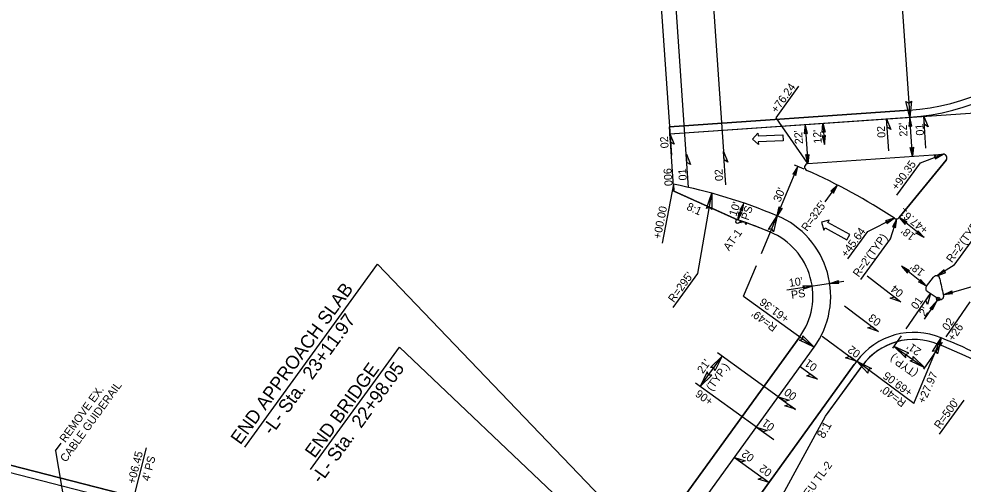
# Model space of a CAD drawing. Extents: x 1183930 to 1185370, y 573068 to 574871.
# Drawn here: x 1184226 to 1184757, y 574194 to 574455 of the extents above; entities that cross this region are included whole.
import ezdxf

# ---------------------------------------------------------------- set-up
doc = ezdxf.new("R2010")
doc.units = 0
for name, color, linetype in [('E_NCDOT_Terrain_Model_Breakline', 7, 'Continuous'), ('E_NCDOT_Terrain_Model_Contour_Minor', 7, 'Continuous'), ('E_NCDOT_Terrain_Model_Points_High', 7, 'Continuous'), ('E_NCDOT_Vertical_Profile_Ground_Line', 7, 'Continuous'), ('P_NCDOT_Horizontal_Alignment', 7, 'Continuous'), ('P_NCDOT_Horizontal_Alignment_Station_Major_Label', 7, 'Continuous'), ('P_NCDOT_Horizontal_Alignment_Tick_Large', 7, 'Continuous'), ('PC_BEAM', 7, 'Continuous'), ('PC_COLUMN', 7, 'Continuous'), ('PC_OBJECT', 7, 'Continuous'), ('PC_PADFOOTING', 7, 'Continuous'), ('PC_SLAB', 7, 'Continuous'), ('PS_HATCH', 7, 'Continuous')]:
    doc.layers.add(name, color=color, linetype=linetype)

msp = doc.modelspace()

# ---------------------------------------------------------------- linework, layer by layer
for points in [[(1184728.33, 574394.95), (1184727.12, 574399.94), (1184726.57, 574394.8), (1184727.42, 574395.51)], [(1184669.55, 574390.9), (1184668.34, 574395.89), (1184667.79, 574390.75), (1184668.64, 574391.46)], [(1184677.8, 574391.47), (1184678.32, 574396.58), (1184679.57, 574391.56), (1184678.62, 574392.15)], [(1184677.92, 574389.6), (1184679.14, 574384.61), (1184679.69, 574389.75), (1184678.84, 574389.04)], [(1184670.37, 574379.06), (1184669.85, 574373.95), (1184668.6, 574378.96), (1184669.54, 574378.38)], [(1184729.15, 574383.1), (1184728.63, 574377.99), (1184727.38, 574383.01), (1184728.32, 574382.42)], [(1184741.46, 574376.59), (1184745.89, 574379.18), (1184740.81, 574378.23), (1184741.73, 574377.62)], [(1184663.06, 574367.24), (1184664.22, 574372.25), (1184661.42, 574367.9), (1184662.5, 574368.15)], [(1184684.19, 574357.3), (1184686.45, 574361.91), (1184682.74, 574358.32), (1184683.85, 574358.31)], [(1184632.74, 574346.35), (1184630.52, 574342.3), (1184631.24, 574346.89), (1184631.81, 574346.08)], [(1184633.01, 574347.19), (1184633.74, 574351.76), (1184631.5, 574347.69), (1184632.45, 574347.97)], [(1184655.37, 574348.92), (1184652.61, 574344.59), (1184653.75, 574349.63), (1184654.33, 574348.69)], [(1184714.28, 574340.16), (1184718.43, 574343.18), (1184713.47, 574341.73), (1184714.45, 574341.21)], [(1184725.58, 574341.12), (1184721.09, 574343.6), (1184724.5, 574339.72), (1184724.56, 574340.83)], [(1184731.73, 574336.2), (1184735.14, 574332.35), (1184730.6, 574334.83), (1184731.67, 574335.13)], [(1184726.93, 574313.73), (1184722.43, 574316.21), (1184725.84, 574312.33), (1184725.9, 574313.44)], [(1184667.34, 574303.51), (1184672.22, 574305.12), (1184667.05, 574305.26), (1184667.83, 574304.47)], [(1184687.25, 574306.46), (1184682.11, 574306.58), (1184687.02, 574308.22), (1184686.51, 574307.23)], [(1184733.08, 574308.81), (1184736.48, 574304.96), (1184731.95, 574307.44), (1184733.01, 574307.74)], [(1184751.22, 574300.67), (1184746.12, 574300.07), (1184750.75, 574302.37), (1184750.38, 574301.33)], [(1184738.34, 574292.54), (1184741.93, 574296.22), (1184739.78, 574291.51), (1184739.41, 574292.56)], [(1184726.59, 574267.3), (1184718.29, 574271.13), (1184724.84, 574264.68), (1184724.8, 574266.65)], [(1184615.03, 574259.35), (1184621.57, 574265.73), (1184617.56, 574257.46), (1184616.93, 574259.33)], [(1184729.07, 574265.59), (1184735.6, 574259.21), (1184727.24, 574263.03), (1184729.09, 574263.69)], [(1184613.27, 574256.91), (1184609.25, 574248.71), (1184615.85, 574255.1), (1184613.88, 574255.11)]]:
    msp.add_lwpolyline(points, close=True)
msp.add_circle((1184743.06, 574297.86), 1)
at = {"layer": 'E_NCDOT_Terrain_Model_Breakline'}
for p, q in [((1184669.85, 574373.95), (1184745.89, 574379.18)), ((1184721.11, 574343.59), (1184747.56, 574375.9)), ((1184736.48, 574304.96), (1184740.51, 574310.12)), ((1184743.06, 574297.86), (1184736.93, 574302.09))]:
    msp.add_line(p, q, dxfattribs=at)
for centre, radius, start, end in [((1184746.03, 574377.18), 2, 319.9842, 93.9365), ((1184669.98, 574371.95), 2, 93.9365, 246.2761), ((1184538.42, 574072.58), 325, 56.3663, 66.2761), ((1184719.54, 574344.84), 2, 236.3663, 321.3768), ((1184742.08, 574308.88), 2, 9.036, 141.8552), ((1184738.06, 574303.74), 2, 142.078, 235.4598), ((1184816.15, 574320.66), 73, 189.036, 196.3782), ((1184744.2, 574299.51), 2, 235.4604, 16.3782)]:
    msp.add_arc(centre, radius, start, end, dxfattribs=at)
at = {"layer": 'E_NCDOT_Terrain_Model_Contour_Minor'}
for p, q in [((1184720.93, 574489.89), (1184727.12, 574399.94)), ((1184608.03, 574312.15), (1184615.89, 574357.23)), ((1184643.7, 574323.36), (1184652.61, 574344.59)), ((1184716.23, 574331.68), (1184719.85, 574342.87)), ((1184752.08, 574316.81), (1184768.7, 574339.76)), ((1184699.62, 574308.73), (1184716.23, 574331.68)), ((1184633.64, 574299.41), (1184640.9, 574316.69)), ((1184752.08, 574316.81), (1184742.59, 574310.82)), ((1184594.15, 574292.98), (1184608.03, 574312.15)), ((1184633.64, 574299.41), (1184673.34, 574270.68)), ((1184729.47, 574239.08), (1184744.78, 574276.04)), ((1184729.47, 574239.08), (1184697.28, 574262.82)), ((1184743.79, 574221.88), (1184757.66, 574241.05))]:
    msp.add_line(p, q, dxfattribs=at)
for points in [[(1184728.05, 574409.02), (1184727.12, 574399.94), (1184724.9, 574408.86), (1184726.58, 574407.82)], [(1184612.82, 574348.63), (1184615.89, 574357.23), (1184615.91, 574348.04), (1184614.53, 574349.45)], [(1184647.7, 574336.89), (1184652.61, 574344.59), (1184650.58, 574335.62), (1184649.55, 574337.3)], [(1184719.12, 574337.78), (1184719.85, 574342.87), (1184717.43, 574338.3), (1184718.48, 574338.64)], [(1184746.4, 574314.25), (1184742.59, 574310.82), (1184747.37, 574312.77), (1184746.35, 574313.19)], [(1184666.95, 574277.21), (1184673.34, 574270.68), (1184665.07, 574274.69), (1184666.94, 574275.31)], [(1184739.9, 574268.32), (1184744.78, 574276.04), (1184742.79, 574267.07), (1184741.75, 574268.74)], [(1184703.6, 574256.23), (1184697.28, 574262.82), (1184705.51, 574258.74), (1184703.64, 574258.13)]]:
    msp.add_lwpolyline(points, close=True, dxfattribs=at)
at = {"layer": 'E_NCDOT_Terrain_Model_Points_High'}
for p, q in [((1184669.85, 574373.95), (1184745.89, 574379.18)), ((1184747.56, 574375.9), (1184721.11, 574343.59)), ((1184736.48, 574304.96), (1184740.51, 574310.12)), ((1184743.06, 574297.86), (1184736.93, 574302.09))]:
    msp.add_line(p, q, dxfattribs=at)
for centre, radius, start, end in [((1184746.03, 574377.18), 2, 319.9842, 93.9365), ((1184669.98, 574371.95), 2, 93.9365, 246.2761), ((1184538.42, 574072.58), 325, 56.3663, 66.2761), ((1184719.54, 574344.84), 2, 236.3663, 321.3768), ((1184742.08, 574308.88), 2, 9.036, 141.8552), ((1184738.06, 574303.74), 2, 142.078, 235.4598), ((1184816.15, 574320.66), 73, 189.036, 196.3782), ((1184744.2, 574299.51), 2, 235.4604, 16.3782)]:
    msp.add_arc(centre, radius, start, end, dxfattribs=at)
at = {"layer": 'E_NCDOT_Vertical_Profile_Ground_Line'}
for p, q in [((1184726.84, 574403.93), (1184592, 574394.65)), ((1184592, 574394.65), (1184726.84, 574403.93)), ((1184594.49, 574358.48), (1184630.33, 574342.36)), ((1184630.33, 574342.36), (1184594.49, 574358.48)), ((1184449.47, 573978.44), (1184665.23, 574276.54)), ((1184449.47, 573978.44), (1184665.23, 574276.54)), ((1184679.82, 574231.89), (1184699.16, 574258.6)), ((1184679.82, 574231.89), (1184699.16, 574258.6)), ((1184654.62, 574185.97), (1184679.82, 574231.89)), ((1184654.62, 574185.97), (1184679.82, 574231.89)), ((1184144.08, 574224.27), (1184371.09, 574166.16)), ((1184144.08, 574224.27), (1184290.79, 574186.71))]:
    msp.add_line(p, q, dxfattribs=at)
for centre, radius, start, end in [((1184718.19, 574529.63), 126, 273.9365, 316.9078), ((1184718.19, 574529.63), 126, 273.9365, 316.9078), ((1184538.42, 574072.58), 285, 67.2278, 71.188), ((1184538.42, 574072.58), 285, 67.2278, 71.188), ((1184633.64, 574299.41), 39, 324.103, 67.2278), ((1184633.64, 574299.41), 39, 324.103, 67.2278), ((1184729.47, 574239.08), 36, 67.5035, 143.5927), ((1184729.47, 574239.08), 36, 67.5035, 143.5927), ((1184553.46, 573814.09), 496, 55.4598, 67.5035), ((1184553.46, 573814.09), 496, 55.4598, 67.5035), ((1186063.32, 573271.23), 1684, 144.03642, 144.10304), ((1186063.32, 573271.23), 1684, 144.03642, 144.10304)]:
    msp.add_arc(centre, radius, start, end, dxfattribs=at)
at = {"layer": 'P_NCDOT_Horizontal_Alignment'}
for p, q in [((1184592.27, 574390.66), (1184783.93, 574403.85)), ((1184592.27, 574390.66), (1184727.12, 574399.94)), ((1184592.27, 574390.66), (1184727.12, 574399.94)), ((1184594.49, 574358.48), (1184592, 574394.65)), ((1184397.22, 573889.19), (1184673.34, 574270.68)), ((1184405.59, 573859.83), (1184695.92, 574260.95)), ((1184143.08, 574220.4), (1184971.37, 574008.35)), ((1184143.08, 574220.4), (1184977.73, 574006.73))]:
    msp.add_line(p, q, dxfattribs=at)
for centre, radius, start, end in [((1184718.19, 574529.63), 130, 273.9365, 316.9078), ((1184718.19, 574529.63), 130, 273.9365, 316.9078), ((1184538.42, 574072.58), 295, 67.2278, 79.0959), ((1184633.64, 574299.41), 49, 324.103, 67.2278), ((1184729.47, 574239.08), 40, 67.5035, 143.5927), ((1184553.46, 573814.09), 500, 55.4598, 67.5035), ((1186063.32, 573271.23), 1688, 144.02449, 144.10304)]:
    msp.add_arc(centre, radius, start, end, dxfattribs=at)
at = {"layer": 'P_NCDOT_Horizontal_Alignment_Station_Major_Label'}
for p, q in [((1184632.14, 574341.72), (1184630.52, 574342.29)), ((1184631.89, 574341.81), (1184631.62, 574341.05)), ((1184632.55, 574341.58), (1184631.62, 574341.05)), ((1184632.55, 574341.58), (1184631.89, 574341.81)), ((1184631.89, 574341.81), (1184632.28, 574340.82)), ((1184632.02, 574341.77), (1184632.14, 574341.72)), ((1184632.09, 574341.31), (1184634.01, 574341.06)), ((1184635.48, 574340.55), (1184632.14, 574341.72)), ((1184632.28, 574340.82), (1184632.55, 574341.58)), ((1184630.74, 574340.53), (1184631.66, 574341.14)), ((1184631.62, 574341.05), (1184632.28, 574340.82)), ((1184634.82, 574340.78), (1184634.56, 574340.02)), ((1184635.48, 574340.55), (1184634.56, 574340.02)), ((1184634.56, 574340.02), (1184635.22, 574339.79)), ((1184635.48, 574340.55), (1184634.82, 574340.78)), ((1184634.82, 574340.78), (1184635.22, 574339.79)), ((1184635.22, 574339.79), (1184635.48, 574340.55))]:
    msp.add_line(p, q, dxfattribs=at)
msp.add_ellipse((1184630.19, 574341.36), major_axis=(-0.33, -0.937), ratio=0.995379, start_param=3.141593, end_param=7.214552, dxfattribs=at)
at = {"layer": 'P_NCDOT_Horizontal_Alignment_Tick_Large'}
msp.add_line((1184575.38, 574152.4), (1184665.23, 574276.54), dxfattribs=at)
for centre, radius, start, end in [((1184538.42, 574072.58), 285, 67.2278, 70.0887), ((1184633.64, 574299.41), 39, 324.103, 67.2278)]:
    msp.add_arc(centre, radius, start, end, dxfattribs=at)
at = {"layer": 'PC_BEAM'}
for p, q in [((1184638.73, 574387.63), (1184641.75, 574390.94)), ((1184641.75, 574390.94), (1184641.81, 574389.45)), ((1184641.81, 574389.45), (1184655.8, 574389.98)), ((1184655.8, 574389.98), (1184655.93, 574386.69)), ((1184642, 574384.65), (1184638.73, 574387.63)), ((1184655.93, 574386.69), (1184641.94, 574386.15)), ((1184641.94, 574386.15), (1184642, 574384.65)), ((1184681.82, 574342.09), (1184677.57, 574340.9)), ((1184681.1, 574340.77), (1184681.82, 574342.09)), ((1184677.57, 574340.9), (1184678.78, 574336.57)), ((1184678.78, 574336.57), (1184679.5, 574337.89)), ((1184679.5, 574337.89), (1184691.75, 574331.11)), ((1184693.35, 574334), (1184681.1, 574340.77)), ((1184691.75, 574331.11), (1184693.35, 574334))]:
    msp.add_line(p, q, dxfattribs=at)
at = {"layer": 'PC_COLUMN'}
for points in [[(1184735, 574400.41), (1184737.41, 574394.56), (1184735.32, 574395.79)], [(1184714.07, 574398.97), (1184716.48, 574393.12), (1184714.39, 574394.35)], [(1184592.3, 574390.59), (1184594.71, 574384.74), (1184592.62, 574385.97)], [(1184601.51, 574379.19), (1184603.91, 574373.34), (1184601.82, 574374.58)], [(1184622.46, 574380.63), (1184624.86, 574374.79), (1184622.77, 574376.02)], [(1184722.16, 574296.22), (1184716.18, 574298.28), (1184718.48, 574299.03)], [(1184738.74, 574300.84), (1184736.99, 574294.76), (1184736.12, 574297.03)], [(1184709.6, 574279.58), (1184703.59, 574281.56), (1184705.89, 574282.34)], [(1184697.09, 574262.9), (1184691.06, 574264.79), (1184693.34, 574265.61)], [(1184675.19, 574252.83), (1184669.15, 574254.73), (1184671.44, 574255.54)], [(1184653.19, 574242.84), (1184659.22, 574240.95), (1184656.94, 574240.13)], [(1184662.84, 574235.85), (1184656.8, 574237.74), (1184659.09, 574238.56)], [(1184640.9, 574225.81), (1184646.94, 574223.91), (1184644.65, 574223.1)], [(1184628.59, 574208.8), (1184634.62, 574206.9), (1184632.34, 574206.09)], [(1184647.98, 574194.77), (1184641.94, 574196.67), (1184644.23, 574197.48)]]:
    msp.add_lwpolyline(points, close=True, dxfattribs=at)
at = {"layer": 'PC_OBJECT'}
for p, q in [((1184726.84, 574403.93), (1184592, 574394.65)), ((1184592.27, 574390.66), (1184727.12, 574399.94)), ((1184592, 574394.65), (1184592.27, 574390.66)), ((1184594.23, 574362.26), (1184594.49, 574358.48)), ((1184665.23, 574276.54), (1184572.55, 574148.49)), ((1184583.05, 574145.94), (1184673.34, 574270.68)), ((1184695.92, 574260.95), (1184608.09, 574139.6)), ((1184679.82, 574231.89), (1184700.31, 574260.19)), ((1184654.62, 574185.97), (1184679.82, 574231.89)), ((1184143.08, 574220.4), (1184547.76, 574116.8)), ((1184290.79, 574186.71), (1184144.08, 574224.27))]:
    msp.add_line(p, q, dxfattribs=at)
msp.add_lwpolyline([(1184630.14, 574342.44), (1184630.33, 574342.36)], dxfattribs=at)
for centre, radius, start, end in [((1184718.19, 574529.63), 126, 273.9365, 316.9078), ((1184718.19, 574529.63), 130, 273.9365, 316.9078), ((1184538.42, 574072.58), 295, 67.2278, 79.0959), ((1184538.42, 574072.58), 285, 67.2278, 71.188), ((1184633.64, 574299.41), 49, 324.103, 67.2278), ((1184633.64, 574299.41), 39, 324.103, 67.2278), ((1184729.47, 574239.08), 40, 67.5035, 143.5927), ((1184729.47, 574239.08), 36, 67.5035, 144.103), ((1184553.46, 573814.09), 496, 55.4598, 67.5035), ((1184553.46, 573814.09), 500, 55.4598, 67.5035), ((1186063.32, 573271.23), 1688, 144.02449, 144.10304)]:
    msp.add_arc(centre, radius, start, end, dxfattribs=at)
for points in [[(1184594.49, 574358.48), (1184594.97, 574358.26), (1184595.46, 574358.04), (1184595.95, 574357.82), (1184596.43, 574357.6), (1184596.92, 574357.38), (1184597.41, 574357.16), (1184597.9, 574356.94), (1184598.38, 574356.73), (1184598.87, 574356.51), (1184599.36, 574356.29), (1184599.84, 574356.07), (1184600.33, 574355.85), (1184600.82, 574355.63), (1184601.3, 574355.41), (1184601.79, 574355.19), (1184602.28, 574354.97), (1184602.76, 574354.75), (1184603.25, 574354.54), (1184603.74, 574354.32), (1184604.22, 574354.1), (1184604.71, 574353.88), (1184605.2, 574353.66), (1184605.69, 574353.44), (1184606.17, 574353.22), (1184606.37, 574353.13)], [(1184606.37, 574353.13), (1184606.66, 574353), (1184607.15, 574352.78), (1184607.63, 574352.57), (1184608.12, 574352.35), (1184608.61, 574352.13), (1184609.09, 574351.91), (1184609.58, 574351.69), (1184610.07, 574351.47), (1184610.55, 574351.25), (1184611.04, 574351.03), (1184611.53, 574350.81), (1184612.01, 574350.59), (1184612.5, 574350.38), (1184612.99, 574350.16), (1184613.47, 574349.94), (1184613.96, 574349.72), (1184614.45, 574349.5), (1184614.94, 574349.28), (1184615.42, 574349.06), (1184615.91, 574348.84), (1184616.4, 574348.62), (1184616.88, 574348.4), (1184617.37, 574348.19), (1184617.86, 574347.97), (1184618.26, 574347.79)], [(1184618.26, 574347.79), (1184618.34, 574347.75), (1184618.83, 574347.53), (1184619.32, 574347.31), (1184619.8, 574347.09), (1184620.29, 574346.87), (1184620.78, 574346.65), (1184621.26, 574346.43), (1184621.75, 574346.22), (1184622.24, 574346), (1184622.72, 574345.78), (1184623.21, 574345.56), (1184623.7, 574345.34), (1184624.19, 574345.12), (1184624.67, 574344.9), (1184625.16, 574344.68), (1184625.65, 574344.46), (1184626.13, 574344.24), (1184626.62, 574344.03), (1184627.11, 574343.81), (1184627.59, 574343.59), (1184628.08, 574343.37), (1184628.57, 574343.15), (1184629.05, 574342.93), (1184629.54, 574342.71), (1184630.14, 574342.44)]]:
    msp.add_spline(points, degree=3, dxfattribs=at)
at = {"layer": 'PC_PADFOOTING'}
for p, q in [((1184601.48, 574379.26), (1184593.72, 574492.05)), ((1184614.67, 574493.49), (1184622.43, 574380.71)), ((1184651.99, 574399.7), (1184664.78, 574417.37)), ((1184669.85, 574373.95), (1184651.99, 574399.7)), ((1184728.63, 574377.99), (1184727.12, 574399.94)), ((1184668.34, 574395.89), (1184669.85, 574373.95)), ((1184678.32, 574396.58), (1184679.14, 574384.61)), ((1184733.06, 574374.37), (1184745.89, 574379.18)), ((1184719.89, 574356.17), (1184733.06, 574374.37)), ((1184652.61, 574344.59), (1184664.22, 574372.25)), ((1184594.23, 574362.26), (1184587.86, 574329.22)), ((1184679.53, 574352.35), (1184686.45, 574361.91)), ((1184630.52, 574342.29), (1184633.75, 574351.76)), ((1184703.48, 574335.8), (1184718.43, 574343.18)), ((1184735.14, 574332.35), (1184721.09, 574343.6)), ((1184692.34, 574320.41), (1184703.48, 574335.8)), ((1184736.48, 574304.96), (1184722.43, 574316.21)), ((1184658.06, 574303.02), (1184690.12, 574307.76)), ((1184746.12, 574300.07), (1184772.98, 574307.97)), ((1184743.06, 574297.86), (1184735.21, 574286.45)), ((1184717.6, 574270.12), (1184722.47, 574277.2)), ((1184735.07, 574258.47), (1184745.45, 574273.54)), ((1184653.19, 574242.84), (1184618.96, 574267.62)), ((1184718.29, 574271.13), (1184735.59, 574259.22)), ((1184609.25, 574248.71), (1184621.57, 574265.73)), ((1184640.87, 574225.82), (1184606.64, 574250.6)), ((1184297.85, 574214.26), (1184287.86, 574175.24)), ((1184246.79, 574212.53), (1184257.39, 574150.22))]:
    msp.add_line(p, q, dxfattribs=at)
msp.add_lwpolyline([(1184246.79, 574212.53), (1184249.9, 574216.82)], dxfattribs=at)
msp.add_arc((1184538.42, 574072.58), 325, 66.5391, 67.5784, dxfattribs=at)
at = {"layer": 'PC_SLAB'}
for p, q in [((1184736.23, 574382.52), (1184735, 574400.48)), ((1184715.28, 574381.08), (1184714.04, 574399.04)), ((1184602.77, 574360.48), (1184601.48, 574379.26)), ((1184623.72, 574361.92), (1184622.43, 574380.71)), ((1184703.09, 574310.8), (1184722.16, 574296.22)), ((1184725.12, 574281.04), (1184738.74, 574300.84)), ((1184690.35, 574293.92), (1184709.6, 574279.58)), ((1184747.52, 574276.55), (1184761.12, 574296.31)), ((1184677.83, 574276.88), (1184697.25, 574262.78)), ((1184665.5, 574259.85), (1184675.22, 574252.82)), ((1184653.19, 574242.84), (1184662.91, 574235.81)), ((1184640.88, 574225.83), (1184650.6, 574218.8)), ((1184628.56, 574208.82), (1184648, 574194.75))]:
    msp.add_line(p, q, dxfattribs=at)
at = {"layer": 'PS_HATCH'}
for p, q in [((1184579.98, 574569.26), (1184593.1, 574378.69)), ((1184353.18, 574214.54), (1184427.86, 574317.47)), ((1184595.46, 574142.62), (1184427.86, 574317.47)), ((1184427.86, 574317.47), (1184427.86, 574317.47)), ((1184390.25, 574202.03), (1184440.16, 574270.82)), ((1184587.3, 574131.35), (1184440.16, 574270.82)), ((1184455.74, 574256.06), (1184455.74, 574256.06))]:
    msp.add_line(p, q, dxfattribs=at)

# ---------------------------------------------------------------- texts
at = {"layer": 'E_NCDOT_Terrain_Model_Contour_Minor'}
for s, rotation, p in [("R=2'(TYP)", 54.103, (1184750.82, 574317.85)), ("R=2'(TYP)", 54.103, (1184698.36, 574309.78)), ("R=295'", 54.103, (1184594.47, 574295.5)), ('+61.36', 143.5927, (1184659.75, 574287.69)), ("R=49'", 143.5927, (1184652.97, 574282.75)), ('+69.05', 143.5927, (1184729.14, 574246.32)), ('+27.97', 66.1211, (1184735.44, 574238.68)), ("R=40'", 143.5927, (1184725.45, 574240.38)), ("R=500'", 54.103, (1184744.03, 574224.45))]:
    msp.add_text(s, height=4.5, rotation=rotation, dxfattribs=at).set_placement(p)
at = {"layer": 'PC_PADFOOTING'}
for s, height, rotation, p in [('+76.24', 4.5, 54.103, (1184652.28, 574401.92)), ("22'", 4.5, 93.9365, (1184725.87, 574389.25)), ("22'", 4.5, 93.9365, (1184667.06, 574385.03)), ("12'", 4.5, 93.9365, (1184677.66, 574385.28)), ('+90.35', 4.5, 54.103, (1184720.02, 574358.54)), ("30'", 4.5, 67.2278, (1184654.25, 574351.92)), ("10'", 4.5, 71.1464, (1184629.52, 574343.95)), ("R=325'", 4.5, 54.103, (1184669.37, 574335.51)), ('+00.00', 4.5, 78.7944, (1184587.1, 574331.28)), ('8:1', 4.5, 335.7844, (1184601.25, 574348.12)), ('PS', 4.5, 71.1464, (1184636.37, 574341.69)), ('+47.61', 4.5, 141.3173, (1184737.86, 574337.5)), ('+45.64', 4.5, 54.103, (1184691.61, 574320.82)), ("18'", 4.5, 141.3173, (1184730.7, 574333.72)), ("18'", 4.5, 141.3173, (1184735.8, 574313.58)), ("10'", 4.5, 8.4163, (1184659.5, 574304.6)), ('PS', 4.5, 8.4163, (1184660.72, 574297.86)), ("2'", 4.5, 55.4598, (1184735.6, 574287.63)), ('+26', 4.5, 55.4598, (1184751.7, 574273.68)), ("21'", 4.5, 145.4598, (1184733.94, 574269.26)), ('(TYP.)', 4.5, 145.4598, (1184732.17, 574257.18)), ("21'", 4.5, 54.103, (1184610.81, 574255.54)), ('(TYP.)', 4.5, 54.103, (1184615.8, 574245.77)), ('REMOVE EX.', 4.5, 54.0376, (1184252.32, 574216.78)), ('CABLE GUIDERAIL', 4.5, 54.0376, (1184252.66, 574205.76)), ('+06', 4.5, 144.103, (1184616.99, 574241.23)), ('8:1', 5, 61.1127, (1184678.89, 574219.04)), ('+06.45', 4.5, 75.6405, (1184291.43, 574193.57)), ("4' PS", 4.5, 75.6405, (1184299.56, 574195.15))]:
    msp.add_text(s, height=height, rotation=rotation, dxfattribs=at).set_placement(p)
at = {"layer": 'PC_SLAB'}
for s, rotation, p in [('02', 93.9365, (1184713.51, 574388.54)), ('01', 93.9365, (1184735.16, 574389.81)), ('02', 93.9365, (1184591.57, 574382.67)), ('006', 93.9365, (1184593.78, 574361.45)), ('01', 93.9365, (1184601.77, 574364.6)), ('02', 93.9365, (1184622.26, 574364.27)), ('04', 141.0877, (1184723.93, 574301.88)), ('01', 55.4598, (1184731.09, 574291.58)), ('03', 142.3544, (1184711.36, 574285.72)), ('02', 55.4598, (1184748.61, 574279.7)), ('02', 144.103, (1184699.8, 574268.02)), ('01', 144.103, (1184675.5, 574260.41)), ('00', 144.103, (1184664.01, 574244.12)), ('01', 144.103, (1184651.52, 574226.83)), ('02', 144.103, (1184640.07, 574209.53)), ('02', 144.103, (1184650.03, 574201.22))]:
    msp.add_text(s, height=4.5, rotation=rotation, dxfattribs=at).set_placement(p)
at = {"layer": 'PS_HATCH'}
for s, height, p in [('AT-1', 4.5, (1184625.5, 574324.51)), ('END APPROACH SLAB', 7.5, (1184350.75, 574215.48)), ('-L- Sta.  23+11.97', 7.5, (1184368.53, 574220.83)), ('END BRIDGE', 7.5, (1184392.52, 574207.96)), ('-L- Sta.  22+98.05', 7.5, (1184396.02, 574193.64)), ('GREU TL-2 ', 4.5, (1184665.32, 574179.08))]:
    msp.add_text(s, height=height, rotation=54.0376, dxfattribs=at).set_placement(p)

doc.saveas('drawing.dxf')
